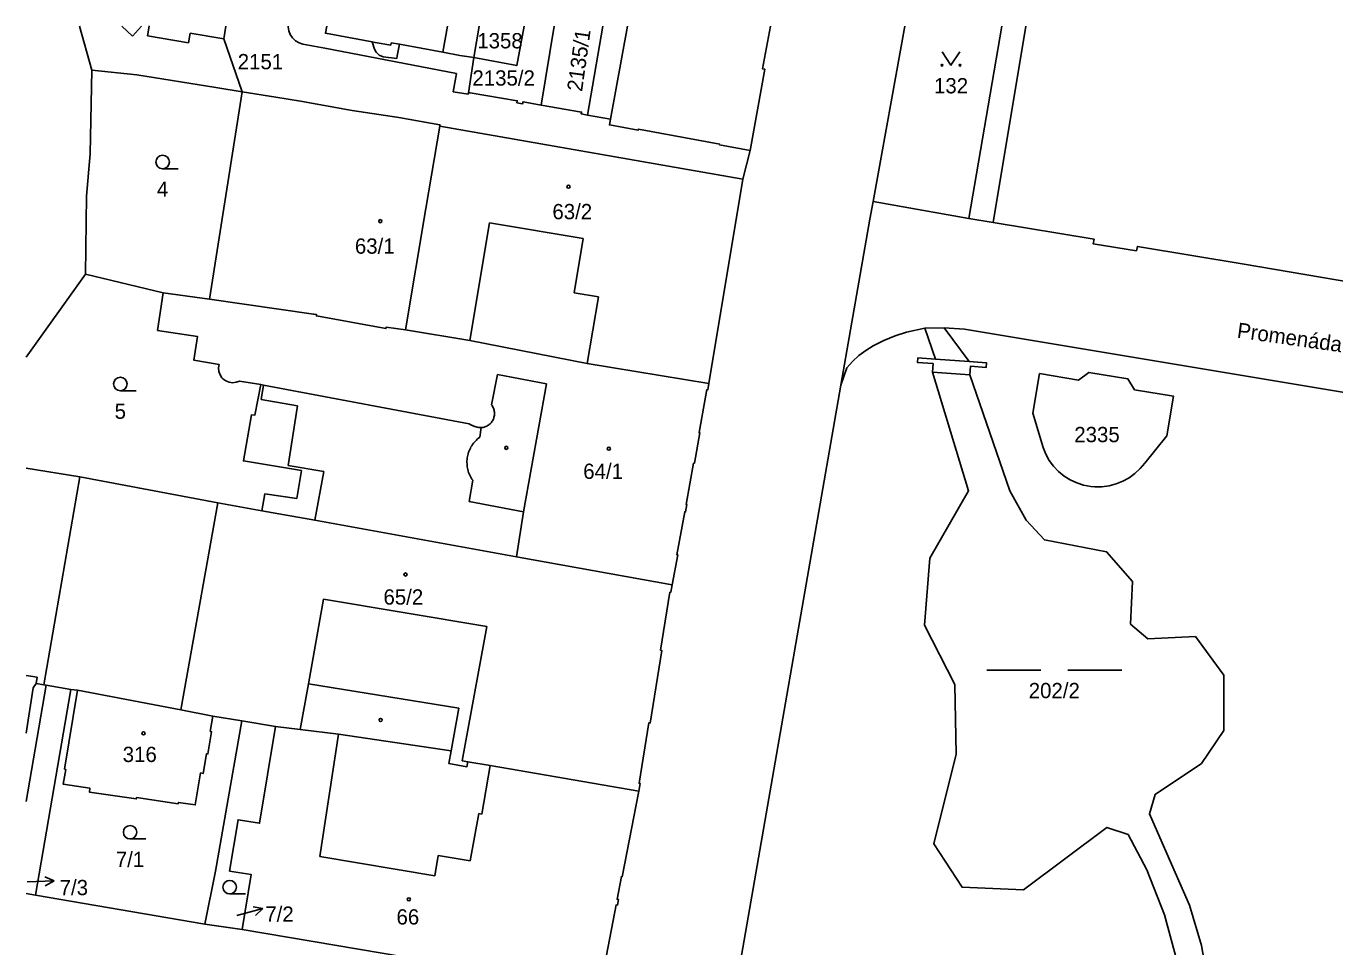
# Model space of a CAD drawing. Extents: x -866441 to -866144, y -1037389 to -1036968.
# Drawn here: x -866440.8 to -866295.1, y -1037070.9 to -1036968.4 of the extents above; entities that cross this region are included whole.
import ezdxf

# ---------------------------------------------------------------- set-up
doc = ezdxf.new("R2010")
doc.units = 0
for name, color, linetype in [('Hranice parcel', 7, 'Continuous'), ('Parcelní čísla', 7, 'Continuous'), ('Pop  PČ popisy', 7, 'Continuous'), ('Vnitřní kresba', 7, 'Continuous'), ('Značky budov', 7, 'Continuous'), ('Značky kultur', 7, 'Continuous')]:
    doc.layers.add(name, color=color, linetype=linetype)

msp = doc.modelspace()

# ---------------------------------------------------------------- linework, layer by layer
at = {"layer": 'Hranice parcel'}
for p, q in [((-866390.96, -1036971.84), (-866390.37, -1036968.36)), ((-866382.01, -1036968.36), (-866383.47, -1036977.16)), ((-866343.01, -1036968.36), (-866346.54, -1036987.9)), ((-866416.75, -1036975.66), (-866418.8, -1036969.77)), ((-866409.99, -1036970.35), (-866407.53, -1036970.82)), ((-866391.57, -1036975.77), (-866390.96, -1036971.84)), ((-866419.68, -1036975.19), (-866416.75, -1036975.66)), ((-866416.75, -1036975.66), (-866420.38, -1036998.77)), ((-866413, -1036976.27), (-866416.75, -1036975.66)), ((-866394.76, -1036979.49), (-866361.01, -1036985.4)), ((-866360.22, -1036982.21), (-866361.01, -1036985.4)), ((-866361.01, -1036985.4), (-866364.81, -1037008.17)), ((-866346.9, -1036989.87), (-866346.54, -1036987.9)), ((-866346.54, -1036987.9), (-866335.86, -1036989.76)), ((-866350.11, -1037008.35), (-866346.9, -1036989.87)), ((-866333.15, -1036990.23), (-866335.86, -1036989.76)), ((-866434.17, -1036995.97), (-866440.78, -1037005.21)), ((-866434.17, -1036995.97), (-866425.53, -1036998.04)), ((-866425.53, -1036998.04), (-866426.18, -1037002.25)), ((-866420.38, -1036998.77), (-866425.53, -1036998.04)), ((-866340.79, -1037002.01), (-866342.81, -1037002.42)), ((-866340.79, -1037002.01), (-866338.61, -1037001.97)), ((-866339.57, -1037005.44), (-866340.79, -1037002.01)), ((-866338.61, -1037001.97), (-866335.84, -1037005.72)), ((-866349.47, -1037006.41), (-866350.11, -1037008.35)), ((-866350.11, -1037008.35), (-866366.04, -1037099.65)), ((-866327.62, -1037015.28), (-866328.75, -1037011.45)), ((-866313.84, -1037013.98), (-866316.3, -1037017.01)), ((-866440.78, -1037017.58), (-866434.8, -1037018.56)), ((-866434.8, -1037018.56), (-866438.83, -1037041.7)), ((-866440.78, -1037054.7), (-866438.56, -1037041.75)), ((-866440, -1037042.06), (-866439.67, -1037041.55)), ((-866435.83, -1037042.25), (-866439.73, -1037065.12)), ((-866439.67, -1037041.55), (-866438.83, -1037041.7)), ((-866438.83, -1037041.7), (-866438.56, -1037041.75)), ((-866438.56, -1037041.75), (-866435.83, -1037042.25)), ((-866436.52, -1037051.12), (-866435.06, -1037042.3)), ((-866435.83, -1037042.25), (-866435.06, -1037042.3)), ((-866420.01, -1037045.19), (-866416.8, -1037045.74)), ((-866416.8, -1037045.74), (-866413.03, -1037046.34)), ((-866439.73, -1037065.12), (-866440.78, -1037064.94)), ((-866439.73, -1037065.12), (-866420.9, -1037068.35)), ((-866420.9, -1037068.35), (-866416.74, -1037068.97)), ((-866416.74, -1037068.97), (-866376.95, -1037075.67))]:
    msp.add_line(p, q, dxfattribs=at)
for points in [[(-866434.83, -1036968.36), (-866433.47, -1036973.26)], [(-866418.8, -1036969.77), (-866418.55, -1036968.36)], [(-866411.62, -1036968.36), (-866411.63, -1036968.43), (-866411.56, -1036968.88), (-866411.4, -1036969.29), (-866411.14, -1036969.66), (-866410.81, -1036969.98), (-866410.42, -1036970.21), (-866409.99, -1036970.35)], [(-866407.34, -1036968.36), (-866407.48, -1036969.15), (-866402.26, -1036970.11)], [(-866385.35, -1036968.36), (-866386.18, -1036972.75), (-866390.96, -1036971.84)], [(-866376.62, -1036968.36), (-866378.33, -1036978.27)], [(-866357.95, -1036968.36), (-866358.82, -1036973.12), (-866358.58, -1036973.16), (-866360.22, -1036982.21)], [(-866335.86, -1036989.76), (-866332.22, -1036968.36)], [(-866329.52, -1036968.36), (-866333.15, -1036990.23)], [(-866407.53, -1036970.82), (-866392.9, -1036973.64), (-866393.26, -1036975.66), (-866391.59, -1036975.93), (-866391.57, -1036975.77)], [(-866402.26, -1036970.11), (-866402.03, -1036970.91), (-866401.85, -1036971.26), (-866401.51, -1036971.6), (-866401.04, -1036971.76), (-866399.55, -1036971.97)], [(-866399.55, -1036971.97), (-866399.49, -1036971.67), (-866399.25, -1036970.37), (-866394.4, -1036971.26), (-866392.53, -1036971.61), (-866390.96, -1036971.84)], [(-866433.47, -1036973.26), (-866433.67, -1036982.58), (-866434.07, -1036987.29), (-866434.17, -1036995.97)], [(-866433.47, -1036973.26), (-866428.48, -1036973.76), (-866419.68, -1036975.19)], [(-866394.76, -1036979.49), (-866394.73, -1036979.34), (-866399.31, -1036978.53), (-866404.5, -1036977.74), (-866410.24, -1036976.72), (-866413, -1036976.27)], [(-866383.47, -1036977.16), (-866385.49, -1036976.78), (-866385.53, -1036976.99), (-866386.17, -1036976.88), (-866386.13, -1036976.66), (-866391.37, -1036975.8), (-866391.57, -1036975.77)], [(-866378.33, -1036978.27), (-866379.01, -1036978.14), (-866378.98, -1036977.93), (-866383.47, -1036977.16)], [(-866360.22, -1036982.21), (-866363.62, -1036981.59), (-866363.6, -1036981.49), (-866372.65, -1036979.84), (-866372.67, -1036979.94), (-866375.87, -1036979.36), (-866375.75, -1036978.72), (-866378.33, -1036978.27)], [(-866398.55, -1037002.17), (-866396.29, -1036988.66), (-866395.67, -1036984.94), (-866394.76, -1036979.49)], [(-866333.15, -1036990.23), (-866321.94, -1036992.09), (-866322.04, -1036992.59), (-866317.22, -1036993.37), (-866317.12, -1036992.89), (-866305.22, -1036994.87)], [(-866305.22, -1036994.87), (-866286.5, -1036998.04), (-866279.05, -1036999.29), (-866279.07, -1036999.44), (-866274.61, -1037000.19), (-866274.59, -1037000.04), (-866267.61, -1037001.21), (-866248.62, -1037004.54), (-866235.67, -1037006.74), (-866235.69, -1037006.83), (-866223.91, -1037008.83), (-866223.89, -1037008.71), (-866219.08, -1037009.53), (-866210.68, -1037011.04)], [(-866420.38, -1036998.77), (-866408.79, -1037000.42), (-866408.46, -1037000.48), (-866408.49, -1037000.63), (-866400.74, -1037002.03), (-866400.71, -1037001.88), (-866398.55, -1037002.17)], [(-866426.18, -1037002.25), (-866421.73, -1037002.92), (-866422.13, -1037005.55), (-866419.3, -1037006.02)], [(-866364.81, -1037008.17), (-866378.34, -1037005.91), (-866391.4, -1037003.37), (-866398.55, -1037002.17)], [(-866342.81, -1037002.42), (-866344.08, -1037002.84), (-866345.32, -1037003.36), (-866346.51, -1037003.97), (-866347.34, -1037004.47), (-866348.11, -1037005.03), (-866348.82, -1037005.69), (-866349.47, -1037006.41)], [(-866255.23, -1037015.93), (-866256.61, -1037015.56), (-866281.38, -1037011.26), (-866336.35, -1037002.11), (-866338.61, -1037001.97)], [(-866312.63, -1037072.83), (-866314.11, -1037067.33), (-866316.07, -1037062.32), (-866318.16, -1037058.39), (-866320.5, -1037057.6), (-866329.79, -1037064.54), (-866336.63, -1037064.25), (-866339.77, -1037059.42), (-866337.28, -1037049.42), (-866337.45, -1037041.66), (-866340.8, -1037035.07), (-866340.21, -1037027.59), (-866335.91, -1037020.11), (-866339.93, -1037006.88), (-866339.86, -1037005.93), (-866341.59, -1037005.8), (-866341.55, -1037005.3), (-866339.57, -1037005.44)], [(-866335.84, -1037005.72), (-866333.9, -1037005.86), (-866333.94, -1037006.36), (-866335.69, -1037006.23), (-866335.76, -1037007.19), (-866331.31, -1037020.1), (-866329.5, -1037023.37), (-866327.46, -1037025.57), (-866320.55, -1037026.9), (-866317.67, -1037030.21), (-866317.89, -1037034.94), (-866315.95, -1037036.58), (-866310.65, -1037036.33), (-866307.51, -1037040.65), (-866307.5, -1037046.81), (-866309.99, -1037050.49), (-866315.12, -1037053.91), (-866315.77, -1037056.08), (-866313.58, -1037061.11), (-866311.31, -1037066.24), (-866310, -1037070.73), (-866309.37, -1037074.15)], [(-866419.3, -1037006.02), (-866419.37, -1037006.41), (-866419.34, -1037006.81), (-866419.21, -1037007.18), (-866418.99, -1037007.52), (-866418.89, -1037007.62), (-866418.58, -1037007.86), (-866418.21, -1037008.01), (-866417.82, -1037008.07), (-866417.42, -1037008.02), (-866417.05, -1037007.88)], [(-866328.75, -1037011.45), (-866328, -1037007.05), (-866323.67, -1037007.78), (-866322.51, -1037006.92), (-866318.18, -1037007.65), (-866317.42, -1037008.85), (-866313.09, -1037009.58), (-866313.84, -1037013.98)], [(-866417.05, -1037007.88), (-866414.68, -1037008.28), (-866415.33, -1037011.68), (-866415.7, -1037011.64), (-866416.6, -1037016.78), (-866410.15, -1037017.85), (-866410.68, -1037020.95), (-866414.23, -1037020.46), (-866414.55, -1037022.32)], [(-866368.9, -1037030.57), (-866368.26, -1037027.25), (-866368.36, -1037027.23), (-866367.49, -1037022.44), (-866367.39, -1037022.45), (-866367.25, -1037021.64), (-866367.34, -1037021.62), (-866366.51, -1037017.02), (-866366.41, -1037017.04), (-866365.8, -1037013.65), (-866365.9, -1037013.63), (-866365.03, -1037008.84), (-866364.93, -1037008.86), (-866364.81, -1037008.17)], [(-866316.3, -1037017.01), (-866316.81, -1037017.63), (-866317.4, -1037018.18), (-866318.05, -1037018.65), (-866318.75, -1037019.04), (-866319.49, -1037019.34), (-866320.27, -1037019.54), (-866321.07, -1037019.65), (-866321.87, -1037019.65), (-866322.31, -1037019.61), (-866323.1, -1037019.47), (-866323.86, -1037019.22), (-866324.59, -1037018.88), (-866325.27, -1037018.46), (-866325.89, -1037017.95), (-866326.45, -1037017.37), (-866326.92, -1037016.72), (-866327.32, -1037016.02), (-866327.62, -1037015.28)], [(-866414.55, -1037022.32), (-866419.45, -1037021.43), (-866434.8, -1037018.56)], [(-866414.55, -1037022.32), (-866408.66, -1037023.38), (-866386.21, -1037027.44), (-866368.9, -1037030.57)], [(-866372.61, -1037053.54), (-866372.47, -1037052.69), (-866372.57, -1037052.67), (-866371.49, -1037045.96), (-866371.34, -1037045.98), (-866370.03, -1037037.89), (-866370.18, -1037037.86), (-866369.14, -1037031.4), (-866369.04, -1037031.41), (-866368.9, -1037030.57)], [(-866440.78, -1037040.69), (-866439.56, -1037040.87), (-866439.67, -1037041.55)], [(-866440.78, -1037047.1), (-866440, -1037042.06)], [(-866435.06, -1037042.3), (-866423.56, -1037044.51), (-866420.01, -1037045.19)], [(-866420.01, -1037045.19), (-866420.3, -1037046.91), (-866420.15, -1037046.93), (-866420.56, -1037049.4), (-866420.71, -1037049.38), (-866421.07, -1037051.57), (-866421.37, -1037051.52), (-866421.96, -1037055.08), (-866423.84, -1037054.8), (-866423.87, -1037054.97), (-866428.52, -1037054.27), (-866428.54, -1037054.42), (-866433.74, -1037053.65), (-866433.68, -1037053.23), (-866436.65, -1037052.79), (-866436.38, -1037051.14), (-866436.52, -1037051.12)], [(-866420.9, -1037068.35), (-866419.73, -1037062.48), (-866416.8, -1037045.74)], [(-866413.03, -1037046.34), (-866414.8, -1037057.12), (-866417.2, -1037056.73), (-866418.14, -1037062.46), (-866415.74, -1037062.85), (-866416.74, -1037068.97)], [(-866413.03, -1037046.34), (-866410.28, -1037046.68), (-866406.01, -1037047.2), (-866393.48, -1037049.07), (-866393.73, -1037050.49), (-866391.74, -1037050.83), (-866391.63, -1037050.29), (-866389.13, -1037050.7), (-866372.61, -1037053.54)], [(-866376.95, -1037075.67), (-866375.14, -1037066.22), (-866374.99, -1037066.24), (-866374.87, -1037065.62), (-866375.02, -1037065.59), (-866374.54, -1037063.06), (-866374.44, -1037063.08), (-866372.61, -1037053.54)]]:
    msp.add_lwpolyline(points, dxfattribs=at)
at = {"layer": 'Pop  PČ popisy'}
for p, q in [((-866440.68, -1037063.66), (-866437.68, -1037063.56)), ((-866437.68, -1037063.56), (-866438.7, -1037063.09)), ((-866437.68, -1037063.56), (-866438.66, -1037064.09)), ((-866417.33, -1037067.42), (-866414.43, -1037066.64)), ((-866414.43, -1037066.64), (-866415.53, -1037066.42)), ((-866414.43, -1037066.64), (-866415.27, -1037067.39))]:
    msp.add_line(p, q, dxfattribs=at)
at = {"layer": 'Vnitřní kresba'}
for p, q in [((-866428.96, -1036969.48), (-866430.14, -1036968.36)), ((-866427.93, -1036968.36), (-866428.96, -1036969.48)), ((-866427.29, -1036969.45), (-866427.11, -1036968.36)), ((-866422.73, -1036970.22), (-866427.29, -1036969.45)), ((-866427.11, -1036968.36), (-866427.13, -1036968.36)), ((-866422.55, -1036969.13), (-866422.73, -1036970.22)), ((-866418.8, -1036969.77), (-866422.55, -1036969.13)), ((-866394.4, -1036971.26), (-866393.88, -1036968.36)), ((-866375.75, -1036978.72), (-866373.86, -1036968.36)), ((-866402.26, -1036970.11), (-866401.96, -1036970.17)), ((-866401.96, -1036970.17), (-866400.21, -1036970.49)), ((-866400.21, -1036970.49), (-866400.16, -1036970.2)), ((-866400.16, -1036970.2), (-866399.25, -1036970.37)), ((-866391.4, -1037003.37), (-866389.21, -1036990.25)), ((-866389.21, -1036990.25), (-866378.78, -1036991.99)), ((-866378.78, -1036991.99), (-866379.8, -1036998.06)), ((-866379.8, -1036998.06), (-866377.1, -1036998.51)), ((-866377.1, -1036998.51), (-866378.34, -1037005.91)), ((-866335.84, -1037005.72), (-866339.57, -1037005.44)), ((-866389, -1037010.53), (-866388.34, -1037007.16)), ((-866388.34, -1037007.16), (-866382.86, -1037008.19)), ((-866335.76, -1037007.19), (-866339.93, -1037006.88)), ((-866414.68, -1037008.28), (-866414.36, -1037008.33)), ((-866414.36, -1037008.33), (-866414.64, -1037009.93)), ((-866414.36, -1037008.33), (-866391.49, -1037012.65)), ((-866385.44, -1037022.43), (-866382.86, -1037008.19)), ((-866414.64, -1037009.93), (-866410.6, -1037010.66)), ((-866410.6, -1037010.66), (-866411.62, -1037017.27)), ((-866390.3, -1037014.13), (-866390.16, -1037013.07)), ((-866411.62, -1037017.27), (-866407.66, -1037017.97)), ((-866407.66, -1037017.97), (-866408.66, -1037023.38)), ((-866391.48, -1037021.3), (-866391.09, -1037018.93)), ((-866419.45, -1037021.43), (-866423.56, -1037044.51)), ((-866385.44, -1037022.43), (-866391.48, -1037021.3)), ((-866386.21, -1037027.44), (-866385.44, -1037022.43)), ((-866409.38, -1037041.59), (-866407.71, -1037032.18)), ((-866407.71, -1037032.18), (-866389.5, -1037035.21)), ((-866389.5, -1037035.21), (-866392.25, -1037050.17)), ((-866410.28, -1037046.68), (-866409.38, -1037041.59)), ((-866409.38, -1037041.59), (-866392.65, -1037044.3)), ((-866392.65, -1037044.3), (-866393.48, -1037049.07)), ((-866406.01, -1037047.2), (-866408.09, -1037060.85)), ((-866391.63, -1037050.29), (-866392.25, -1037050.17)), ((-866390.06, -1037056.11), (-866389.13, -1037050.7)), ((-866391.36, -1037061.3), (-866390.4, -1037056.04)), ((-866390.4, -1037056.04), (-866390.06, -1037056.11)), ((-866408.09, -1037060.85), (-866395.3, -1037063)), ((-866394.92, -1037060.73), (-866395.3, -1037063)), ((-866392.7, -1037061.08), (-866394.92, -1037060.73)), ((-866392.7, -1037061.08), (-866391.36, -1037061.3))]:
    msp.add_line(p, q, dxfattribs=at)
for points in [[(-866389, -1037010.53), (-866388.94, -1037010.62), (-866388.88, -1037010.71), (-866388.83, -1037010.81), (-866388.78, -1037010.91), (-866388.74, -1037011.02), (-866388.71, -1037011.12), (-866388.69, -1037011.23), (-866388.68, -1037011.34), (-866388.67, -1037011.45), (-866388.67, -1037011.56), (-866388.68, -1037011.67), (-866388.69, -1037011.78), (-866388.72, -1037011.89), (-866388.75, -1037012), (-866388.79, -1037012.1), (-866388.83, -1037012.2), (-866388.89, -1037012.3), (-866388.95, -1037012.39), (-866389.01, -1037012.48), (-866389.08, -1037012.57), (-866389.16, -1037012.64), (-866389.24, -1037012.72), (-866389.33, -1037012.78), (-866389.43, -1037012.84), (-866389.52, -1037012.9), (-866389.62, -1037012.95), (-866389.73, -1037012.99), (-866389.83, -1037013.02), (-866389.94, -1037013.04), (-866390.05, -1037013.06), (-866390.16, -1037013.07)], [(-866391.49, -1037012.65), (-866391.37, -1037012.72), (-866391.24, -1037012.79), (-866391.11, -1037012.84), (-866390.98, -1037012.9), (-866390.85, -1037012.94), (-866390.72, -1037012.98), (-866390.58, -1037013.02), (-866390.44, -1037013.04), (-866390.3, -1037013.06), (-866390.16, -1037013.07)], [(-866391.09, -1037018.93), (-866391.18, -1037018.8), (-866391.27, -1037018.66), (-866391.34, -1037018.51), (-866391.42, -1037018.36), (-866391.48, -1037018.21), (-866391.54, -1037018.06), (-866391.59, -1037017.91), (-866391.63, -1037017.75), (-866391.67, -1037017.59), (-866391.69, -1037017.43), (-866391.71, -1037017.26), (-866391.72, -1037017.1), (-866391.73, -1037016.94), (-866391.73, -1037016.77), (-866391.71, -1037016.61), (-866391.7, -1037016.45), (-866391.67, -1037016.29), (-866391.64, -1037016.13), (-866391.59, -1037015.97), (-866391.55, -1037015.81), (-866391.49, -1037015.66), (-866391.42, -1037015.51), (-866391.35, -1037015.36), (-866391.28, -1037015.22), (-866391.19, -1037015.08), (-866391.1, -1037014.94), (-866391, -1037014.81), (-866390.9, -1037014.68), (-866390.79, -1037014.56), (-866390.68, -1037014.45), (-866390.56, -1037014.33), (-866390.43, -1037014.23), (-866390.3, -1037014.13)]]:
    msp.add_lwpolyline(points, dxfattribs=at)
at = {"layer": 'Značky budov'}
for centre in [(-866380.43, -1036986.24), (-866401.37, -1036990.07), (-866387.35, -1037015.32), (-866375.94, -1037015.42), (-866398.57, -1037029.43), (-866401.34, -1037045.62), (-866427.73, -1037047.12), (-866398.2, -1037065.6)]:
    msp.add_circle(centre, 0.175, dxfattribs=at)
at = {"layer": 'Značky kultur'}
for p, q in [((-866425.6, -1036984.24), (-866423.85, -1036984.24)), ((-866430.3, -1037008.96), (-866428.55, -1037008.96)), ((-866333.86, -1037040.07), (-866327.86, -1037040.07)), ((-866324.86, -1037040.07), (-866318.86, -1037040.07)), ((-866429.22, -1037058.88), (-866427.47, -1037058.88)), ((-866418.14, -1037065), (-866416.39, -1037065))]:
    msp.add_line(p, q, dxfattribs=at)
msp.add_lwpolyline([(-866338.86, -1036971.21), (-866337.86, -1036972.71), (-866336.86, -1036971.21)], dxfattribs=at)
for centre, radius in [((-866338.86, -1036972.71), 0.1), ((-866336.86, -1036972.71), 0.1), ((-866425.6, -1036983.49), 0.75), ((-866430.3, -1037008.21), 0.75), ((-866429.22, -1037058.13), 0.75), ((-866418.14, -1037064.25), 0.75)]:
    msp.add_circle(centre, radius, dxfattribs=at)

# ---------------------------------------------------------------- texts
at = {"layer": 'Parcelní čísla'}
for s, p in [('1358', (-866390.58, -1036970.83)), ('2151', (-866417.24, -1036973.16)), ('2135/2', (-866391.12, -1036974.98)), ('132', (-866339.75, -1036975.84)), ('4', (-866426.24, -1036987.36)), ('63/2', (-866382.22, -1036989.86)), ('63/1', (-866404.2, -1036993.7)), ('5', (-866430.94, -1037012.09)), ('2335', (-866324.14, -1037014.69)), ('64/1', (-866378.79, -1037018.78)), ('65/2', (-866401.02, -1037032.78)), ('202/2', (-866329.21, -1037043.2)), ('316', (-866430.04, -1037050.31)), ('7/1', (-866430.81, -1037062.01)), ('7/3', (-866437.06, -1037065.14)), ('7/2', (-866414.17, -1037068.1)), ('66', (-866399.57, -1037068.41))]:
    msp.add_text(s, height=1.7, dxfattribs=at).set_placement(p)
msp.add_text('2135/1', height=1.7, rotation=82, dxfattribs=at).set_placement((-866378.92, -1036975.71))
at = {"layer": 'Pop  PČ popisy'}
msp.add_text('Promenáda Mesta Bad Homburgu', height=1.7, rotation=352, dxfattribs=at).set_placement((-866306.1, -1037003.04))

doc.saveas('drawing.dxf')
